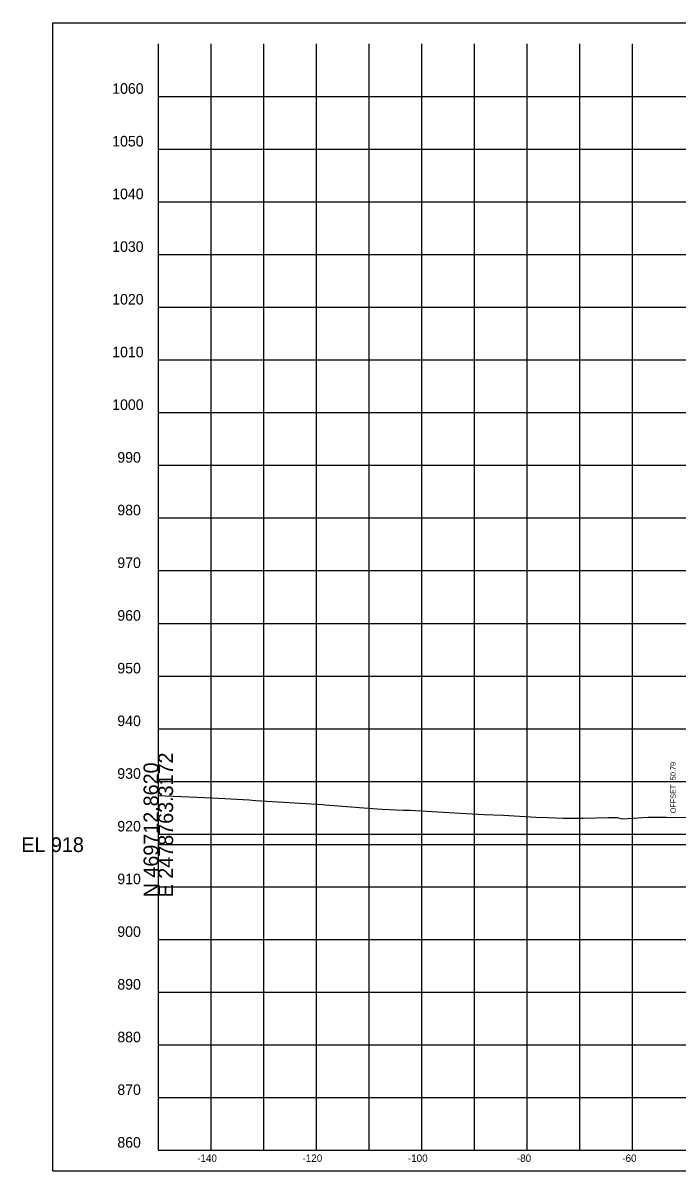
# Model space of a CAD drawing. Extents: x -26 to 2478923, y -10 to 469990.
# Drawn here: x -25.7 to 98.5, y 4438.1 to 4655.9 of the extents above; entities that cross this region are included whole.
import ezdxf

# ---------------------------------------------------------------- set-up
doc = ezdxf.new("R2010")
doc.units = 0
for name, color, linetype in [('DESIGN - SHEET - Corner Text', 7, 'Continuous'), ('DESIGN - SHEET - Light Grid', 7, 'Continuous'), ('DESIGN - SHEET - Linework', 7, 'Continuous'), ('DESIGN - SHEET - Plot Shape', 7, 'Continuous'), ('DESIGN - TYPICAL - Slope Tie Text', 7, 'Continuous'), ('SURVEY - GROUND - Top of Ground', 7, 'Continuous')]:
    doc.layers.add(name, color=color, linetype=linetype)

msp = doc.modelspace()

# ---------------------------------------------------------------- linework, layer by layer
at = {"layer": 'DESIGN - SHEET - Light Grid'}
msp.add_line((0, 4500), (150, 4500), dxfattribs=at)
at = {"layer": 'DESIGN - SHEET - Linework'}
for p, q in [((10, 4442), (10, 4652)), ((10, 4442), (10, 4652)), ((10, 4442), (10, 4652)), ((10, 4442), (10, 4652)), ((20, 4442), (20, 4652)), ((20, 4442), (20, 4652)), ((20, 4442), (20, 4652)), ((20, 4442), (20, 4652)), ((30, 4442), (30, 4652)), ((30, 4442), (30, 4652)), ((30, 4442), (30, 4652)), ((30, 4442), (30, 4652)), ((40, 4442), (40, 4652)), ((40, 4442), (40, 4652)), ((40, 4442), (40, 4652)), ((40, 4442), (40, 4652)), ((50, 4442), (50, 4652)), ((50, 4442), (50, 4652)), ((50, 4442), (50, 4652)), ((50, 4442), (50, 4652)), ((60, 4442), (60, 4652)), ((60, 4442), (60, 4652)), ((60, 4442), (60, 4652)), ((60, 4442), (60, 4652)), ((70, 4442), (70, 4652)), ((70, 4442), (70, 4652)), ((70, 4442), (70, 4652)), ((70, 4442), (70, 4652)), ((80, 4442), (80, 4652)), ((80, 4442), (80, 4652)), ((80, 4442), (80, 4652)), ((80, 4442), (80, 4652)), ((90, 4442), (90, 4652)), ((90, 4442), (90, 4652)), ((90, 4442), (90, 4652)), ((90, 4442), (90, 4652)), ((0, 4642), (300, 4642)), ((0, 4642), (300, 4642)), ((0, 4642), (300, 4642)), ((0, 4642), (300, 4642)), ((0, 4632), (300, 4632)), ((0, 4632), (300, 4632)), ((0, 4632), (300, 4632)), ((0, 4632), (300, 4632)), ((0, 4622), (300, 4622)), ((0, 4622), (300, 4622)), ((0, 4622), (300, 4622)), ((0, 4622), (300, 4622)), ((0, 4612), (300, 4612)), ((0, 4612), (300, 4612)), ((0, 4612), (300, 4612)), ((0, 4612), (300, 4612)), ((0, 4602), (300, 4602)), ((0, 4602), (300, 4602)), ((0, 4602), (300, 4602)), ((0, 4602), (300, 4602)), ((0, 4592), (300, 4592)), ((0, 4592), (300, 4592)), ((0, 4592), (300, 4592)), ((0, 4592), (300, 4592)), ((0, 4582), (300, 4582)), ((0, 4582), (300, 4582)), ((0, 4582), (300, 4582)), ((0, 4582), (300, 4582)), ((0, 4572), (300, 4572)), ((0, 4572), (300, 4572)), ((0, 4572), (300, 4572)), ((0, 4572), (300, 4572)), ((0, 4562), (300, 4562)), ((0, 4562), (300, 4562)), ((0, 4562), (300, 4562)), ((0, 4562), (300, 4562)), ((0, 4552), (300, 4552)), ((0, 4552), (300, 4552)), ((0, 4552), (300, 4552)), ((0, 4552), (300, 4552)), ((0, 4542), (300, 4542)), ((0, 4542), (300, 4542)), ((0, 4542), (300, 4542)), ((0, 4542), (300, 4542)), ((0, 4532), (300, 4532)), ((0, 4532), (300, 4532)), ((0, 4532), (300, 4532)), ((0, 4532), (300, 4532)), ((0, 4522), (300, 4522)), ((0, 4522), (300, 4522)), ((0, 4522), (300, 4522)), ((0, 4522), (300, 4522)), ((0, 4512), (300, 4512)), ((0, 4512), (300, 4512)), ((0, 4512), (300, 4512)), ((0, 4512), (300, 4512)), ((0, 4502), (300, 4502)), ((0, 4502), (300, 4502)), ((0, 4502), (300, 4502)), ((0, 4502), (300, 4502)), ((0, 4492), (300, 4492)), ((0, 4492), (300, 4492)), ((0, 4492), (300, 4492)), ((0, 4492), (300, 4492)), ((0, 4482), (300, 4482)), ((0, 4482), (300, 4482)), ((0, 4482), (300, 4482)), ((0, 4482), (300, 4482)), ((0, 4472), (300, 4472)), ((0, 4472), (300, 4472)), ((0, 4472), (300, 4472)), ((0, 4472), (300, 4472)), ((0, 4462), (300, 4462)), ((0, 4462), (300, 4462)), ((0, 4462), (300, 4462)), ((0, 4462), (300, 4462)), ((0, 4452), (300, 4452)), ((0, 4452), (300, 4452)), ((0, 4452), (300, 4452)), ((0, 4452), (300, 4452))]:
    msp.add_line(p, q, dxfattribs=at)
msp.add_lwpolyline([(0, 4652), (0, 4442), (300, 4442), (300, 4652)], dxfattribs=at)
msp.add_lwpolyline([(0, 4652), (0, 4442), (300, 4442), (300, 4652)], dxfattribs=at)
msp.add_lwpolyline([(0, 4652), (0, 4442), (300, 4442), (300, 4652)], dxfattribs=at)
msp.add_lwpolyline([(0, 4652), (0, 4442), (300, 4442), (300, 4652)], dxfattribs=at)
at = {"layer": 'DESIGN - SHEET - Plot Shape'}
msp.add_lwpolyline([(-20, 4655.94), (320, 4655.94), (320, 4438.06), (-20, 4438.06)], close=True, dxfattribs=at)
msp.add_lwpolyline([(-20, 4655.94), (320, 4655.94), (320, 4438.06), (-20, 4438.06)], close=True, dxfattribs=at)
msp.add_lwpolyline([(-20, 4655.94), (320, 4655.94), (320, 4438.06), (-20, 4438.06)], close=True, dxfattribs=at)
msp.add_lwpolyline([(-20, 4655.94), (320, 4655.94), (320, 4438.06), (-20, 4438.06)], close=True, dxfattribs=at)
at = {"layer": 'SURVEY - GROUND - Top of Ground'}
msp.add_lwpolyline([(0, 4509.31), (1.41, 4509.26), (4.36, 4509.14), (10.31, 4508.88), (17.26, 4508.48), (18.45, 4508.41), (31.22, 4507.6), (31.58, 4507.58), (32.56, 4507.5), (39.03, 4506.99), (42.42, 4506.76), (46.56, 4506.52), (47.81, 4506.56), (52.96, 4506.26), (61.81, 4505.71), (65.49, 4505.59), (71.64, 4505.24), (73.92, 4505.14), (76.87, 4505.04), (80.7, 4505.04), (85.38, 4505.13), (87.12, 4505.16), (88.06, 4504.91), (92.99, 4505.23), (93.5, 4505.24), (96.36, 4505.23), (103.87, 4505.14)], dxfattribs=at)

# ---------------------------------------------------------------- texts
at = {"layer": 'DESIGN - SHEET - Corner Text'}
for s, height, p in [('1060', 2, (-8.75, 4642.5)), ('1060', 2, (-8.75, 4642.5)), ('1060', 2, (-8.75, 4642.5)), ('1060', 2, (-8.75, 4642.5)), ('1050', 2, (-8.75, 4632.5)), ('1050', 2, (-8.75, 4632.5)), ('1050', 2, (-8.75, 4632.5)), ('1050', 2, (-8.75, 4632.5)), ('1040', 2, (-8.75, 4622.5)), ('1040', 2, (-8.75, 4622.5)), ('1040', 2, (-8.75, 4622.5)), ('1040', 2, (-8.75, 4622.5)), ('1030', 2, (-8.75, 4612.5)), ('1030', 2, (-8.75, 4612.5)), ('1030', 2, (-8.75, 4612.5)), ('1030', 2, (-8.75, 4612.5)), ('1020', 2, (-8.75, 4602.5)), ('1020', 2, (-8.75, 4602.5)), ('1020', 2, (-8.75, 4602.5)), ('1020', 2, (-8.75, 4602.5)), ('1010', 2, (-8.75, 4592.5)), ('1010', 2, (-8.75, 4592.5)), ('1010', 2, (-8.75, 4592.5)), ('1010', 2, (-8.75, 4592.5)), ('1000', 2, (-8.75, 4582.5)), ('1000', 2, (-8.75, 4582.5)), ('1000', 2, (-8.75, 4582.5)), ('1000', 2, (-8.75, 4582.5)), ('990', 2, (-7.78, 4572.5)), ('990', 2, (-7.78, 4572.5)), ('990', 2, (-7.78, 4572.5)), ('990', 2, (-7.78, 4572.5)), ('980', 2, (-7.78, 4562.5)), ('980', 2, (-7.78, 4562.5)), ('980', 2, (-7.78, 4562.5)), ('980', 2, (-7.78, 4562.5)), ('970', 2, (-7.78, 4552.5)), ('970', 2, (-7.78, 4552.5)), ('970', 2, (-7.78, 4552.5)), ('970', 2, (-7.78, 4552.5)), ('960', 2, (-7.78, 4542.5)), ('960', 2, (-7.78, 4542.5)), ('960', 2, (-7.78, 4542.5)), ('960', 2, (-7.78, 4542.5)), ('950', 2, (-7.78, 4532.5)), ('950', 2, (-7.78, 4532.5)), ('950', 2, (-7.78, 4532.5)), ('950', 2, (-7.78, 4532.5)), ('940', 2, (-7.78, 4522.5)), ('940', 2, (-7.78, 4522.5)), ('940', 2, (-7.78, 4522.5)), ('940', 2, (-7.78, 4522.5)), ('930', 2, (-7.78, 4512.5)), ('930', 2, (-7.78, 4512.5)), ('930', 2, (-7.78, 4512.5)), ('930', 2, (-7.78, 4512.5)), ('920', 2, (-7.78, 4502.5)), ('920', 2, (-7.78, 4502.5)), ('920', 2, (-7.78, 4502.5)), ('920', 2, (-7.78, 4502.5)), ('910', 2, (-7.78, 4492.5)), ('910', 2, (-7.78, 4492.5)), ('910', 2, (-7.78, 4492.5)), ('910', 2, (-7.78, 4492.5)), ('900', 2, (-7.78, 4482.5)), ('900', 2, (-7.78, 4482.5)), ('900', 2, (-7.78, 4482.5)), ('900', 2, (-7.78, 4482.5)), ('890', 2, (-7.78, 4472.5)), ('890', 2, (-7.78, 4472.5)), ('890', 2, (-7.78, 4472.5)), ('890', 2, (-7.78, 4472.5)), ('880', 2, (-7.78, 4462.5)), ('880', 2, (-7.78, 4462.5)), ('880', 2, (-7.78, 4462.5)), ('880', 2, (-7.78, 4462.5)), ('870', 2, (-7.78, 4452.5)), ('870', 2, (-7.78, 4452.5)), ('870', 2, (-7.78, 4452.5)), ('870', 2, (-7.78, 4452.5)), ('860', 2, (-7.78, 4442.5)), ('860', 2, (-7.78, 4442.5)), ('860', 2, (-7.78, 4442.5)), ('860', 2, (-7.78, 4442.5)), ('-140', 1.4, (7.37, 4439.8)), ('-140', 1.4, (7.37, 4439.8)), ('-140', 1.4, (7.37, 4439.8)), ('-140', 1.4, (7.37, 4439.8)), ('-120', 1.4, (27.37, 4439.8)), ('-120', 1.4, (27.37, 4439.8)), ('-120', 1.4, (27.37, 4439.8)), ('-120', 1.4, (27.37, 4439.8)), ('-100', 1.4, (47.37, 4439.8)), ('-100', 1.4, (47.37, 4439.8)), ('-100', 1.4, (47.37, 4439.8)), ('-100', 1.4, (47.37, 4439.8)), ('-80', 1.4, (68.06, 4439.8)), ('-80', 1.4, (68.06, 4439.8)), ('-80', 1.4, (68.06, 4439.8)), ('-80', 1.4, (68.06, 4439.8)), ('-60', 1.4, (88.06, 4439.8)), ('-60', 1.4, (88.06, 4439.8)), ('-60', 1.4, (88.06, 4439.8)), ('-60', 1.4, (88.06, 4439.8))]:
    msp.add_text(s, height=height, dxfattribs=at).set_placement(p)
at = {"layer": 'DESIGN - SHEET - Light Grid'}
for s, p in [('E 2478763.3172', (2.8, 4490)), ('N 469712.8620', (0, 4490))]:
    msp.add_text(s, height=2.8, rotation=90, dxfattribs=at).set_placement(p)
msp.add_text('EL 918', height=2.8, dxfattribs=at).set_placement((-26, 4498.6))
at = {"layer": 'DESIGN - TYPICAL - Slope Tie Text'}
msp.add_text('OFFSET -50.79', height=1, rotation=90, dxfattribs=at).set_placement((98.21, 4505.94))

doc.saveas('drawing.dxf')
